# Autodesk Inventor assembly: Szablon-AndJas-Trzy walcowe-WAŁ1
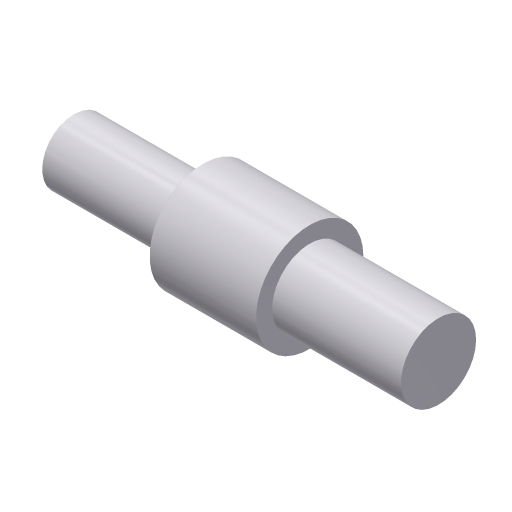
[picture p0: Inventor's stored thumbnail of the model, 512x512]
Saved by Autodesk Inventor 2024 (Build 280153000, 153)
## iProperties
ClientObjectVersion: 1
Company: ATC
Created: 2023-03
Part Number: Szablon-AndJas-Trzy walcowe-WAŁ1
Document SubType Name: Assembly
Designer: Andrzej Jaskulski
Checked By: A.J.
Engr Approved By: Andrzej Jaskulski
Mfg Approved By: Andrzej Jaskulski
Authority: A.J.
Author: Andrzej Jaskulski
Title: A.J.: Kurs R2024-MEP
Revision Number: 1/24
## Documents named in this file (2)
- C:\Users\AndJas\Documents\R2024-MEP\Obszar roboczy\PZ\Szablon-AndJas-Trzy walcowe\Design Accelerator\Szablon-AndJas-Trzy walcowe-WAŁ1.iam
- C:\Users\AndJas\Documents\R2024-MEP\Obszar roboczy\PZ\Szablon-AndJas-Trzy walcowe\Design Accelerator\Szablon-AndJas-Trzy walcowe-WAŁ1.ipt
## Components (1 placed, 1 different names)
1. Wał:1
